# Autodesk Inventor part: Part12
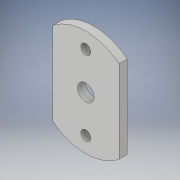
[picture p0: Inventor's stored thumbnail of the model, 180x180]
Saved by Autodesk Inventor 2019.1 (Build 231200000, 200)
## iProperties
Created: 2018-09
Part Number: Part12
Material: Generic
Document SubType Name: Modeling
Designer: drawing
Density: 1 g/cm^3
Appearance: Default
Author: drawing
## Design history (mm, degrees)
sketch "Sketch1"
  geometry: C1 r 20.32 at (0, 0); 1 further point
  constraints: 1 centre point, 1 coincident
  dimensions: "d0" = 40.64 diameter of C1
extrude "Extrusion1" new body sketch "Sketch1" distance "d1" = 3.175; taper "d2" = 0 deg
sketch "Sketch2"
  geometry: 2 further points
  constraints: 1 coincident
hole "Hole1" sketch "Sketch2" at (0, 0) diameter "d3" = 6.35; stored, may be unused: countersink angle "d7" = 82 deg, drill point angle "d9" = 118 deg; dims "d4" = 7.0104, "d5" = 11.1252, "d6" = 6.35, "d8" = 10.9728
sketch "Sketch3"
  geometry: 3 further points
  constraints: 2 vertical alignment
  dimensions: "d10" = 28.575 distance of point (0, 14.287) point (0, -14.287); "d11" = 14.2875 distance of point (0, 0) point (0, 14.287) (= 0.5 x d10)
hole "Hole2" sketch "Sketch3" at (0, 14.287), (0, -14.287) diameter "d12" = 3.81; stored, may be unused: countersink angle "d16" = 82 deg, drill point angle "d18" = 118 deg; dims "d13" = 7.0104, "d14" = 7.1374, "d15" = 3.5052, "d17" = 10.9728
sketch "Sketch4"
  geometry: L1 (-12.7, -38.244)-(12.7, -38.244); L2 (12.7, -38.244)-(12.7, 37.811); L3 (12.7, 37.811)-(-12.7, 37.811); L4 (-12.7, 37.811)-(-12.7, -38.244); L5 (-54.402, 52.786)-(43.857, 52.786); L6 (43.857, 52.786)-(43.857, -66.494); L7 (43.857, -66.494)-(-54.402, -66.494); L8 (-54.402, -66.494)-(-54.402, 52.786); 1 further point
  constraints: 16 end point, 4 parallel, 2 horizontal, 2 perpendicular
  dimensions: "d19" = 25.4 distance of L2.end L3.end; "d20" = 12.7 distance from line of L4 point (0, 0) (= 0.5 x d19)
extrude "Extrusion2" cut sketch "Sketch4" distance "d21" = 3.175; taper "d22" = 0 deg
body "Solid1"
